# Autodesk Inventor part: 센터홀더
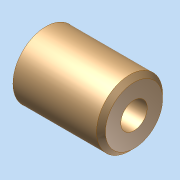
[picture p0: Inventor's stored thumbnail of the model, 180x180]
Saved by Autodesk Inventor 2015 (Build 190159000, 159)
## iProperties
Created: 2026-09
Part Number: 센터홀더
Material: 일반
Document SubType Name: Modeling
Designer: SCD-A06
Density: 1 g/cm^3
Appearance: 기본값
Author: SCD-A06
Author: jhkim
Creation Date: 2026-08-27
Sending System: Autodesk Inventor 2027
Preprocessor: ST-DEVELOPER v20.1
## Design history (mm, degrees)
node "센터홀더1"
node "솔리드1"
node "기준1"
